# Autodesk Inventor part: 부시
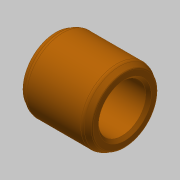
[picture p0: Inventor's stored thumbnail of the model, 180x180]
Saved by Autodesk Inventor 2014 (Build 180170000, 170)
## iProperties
Created: 2018-11
Part Number: 부시
Material: 강철, 연강
Document SubType Name: Modeling
Designer: mduedu
Density: 1 g/cm^3
Appearance: 주황색
d0: 17.000 mm
d1: 26.000 mm
d2: 25.000 mm
d3: 0.00 deg
d14: 1.000 mm
d17: 2.300 mm
d19: 30.00 deg
d20: 2.300 mm
d22: 30.00 deg
d23: 2.000 mm
d24: 0.500 mm
d25: 2.000 mm
d26: 0.500 mm
Author: mduedu
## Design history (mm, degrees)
sketch "스케치1"
  geometry: C1 r 8.5 at (0, 0); C2 r 13 at (0, 0); 1 further point
  constraints: 2 centre point, 2 coincident
  dimensions: "d0" = 17 diameter of C1; "d1" = 26 diameter of C2
extrude "돌출1" new body sketch "스케치1" distance "d2" = 25; taper "d3" = 0 deg
chamfer "모따기4" distance "d14" = 1; stored, may be unused: second distance "d15" = 2, angle "d16" = 15 deg
chamfer "모따기5" distance "d17" = 2.3; stored, may be unused: second distance "d18" = 2, angle "d19" = 30 deg
chamfer "모따기6" distance "d20" = 2.3; stored, may be unused: second distance "d21" = 2, angle "d22" = 30 deg
fillet "모깎기2" dims "d23" = 2, "d24" = 0.5
fillet "모깎기3" dims "d25" = 2, "d26" = 0.5
node "솔리드1"
